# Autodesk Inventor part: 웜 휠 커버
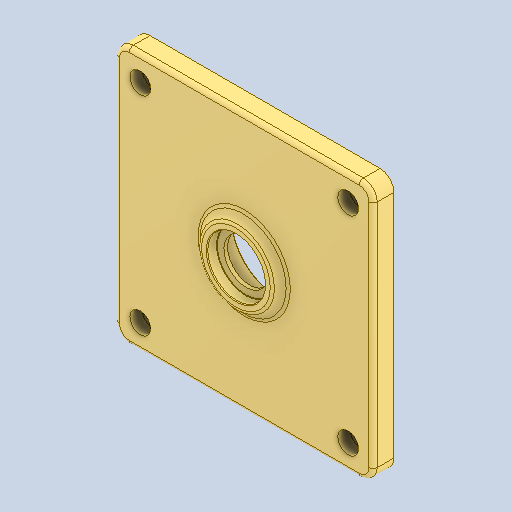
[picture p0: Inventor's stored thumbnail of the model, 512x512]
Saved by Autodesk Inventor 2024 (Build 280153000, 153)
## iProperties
Created: 2025-05
Part Number: 웜 휠 커버
Material: 알루미늄 6061
Document SubType Name: Modeling
Designer: 11
Density: 2.7 g/cm^3
Appearance: 기본값
Author: jhkim
Sending System: Autodesk Inventor 2026
Preprocessor: ST-DEVELOPER v20.1
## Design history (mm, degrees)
node "웜 휠 커버1"
node "솔리드2"
node "솔리드1"
